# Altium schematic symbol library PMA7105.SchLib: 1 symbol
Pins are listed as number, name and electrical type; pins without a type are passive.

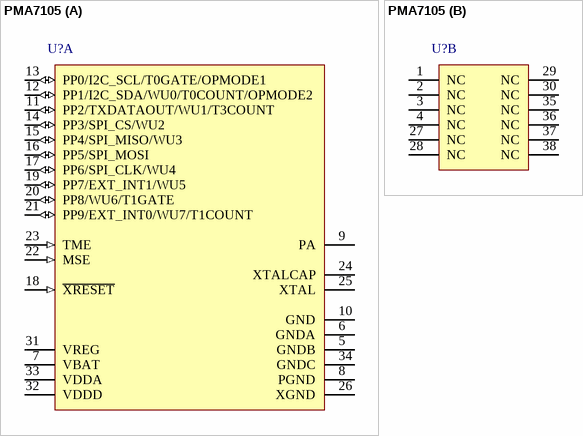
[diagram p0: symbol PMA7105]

## PMA7105
designator U?
RF Transmitter ASK / FSK 315 / 434 / 868 / 915 MHz, Embedded 8051 Microcontroller, 10-bit ADC, 125 kHz ASK LF Receiver, -40 to 85 degC, PG-TSSOP-38, Green; Manufacturer: Infineon; PartNumber: PMA7105; Channel Requirements per Band: Single Channel; Frequency Band: 315 MHz, 434 MHz, 868 MHz, 915 MHz; Green: yes; Transmit Power (at 3V): 5 dBm, 8 dBm, 10 dBm
footprint INF-PG-TSSOP-38_N (SOP, 38-Leads, Body 9.7x4.4 mm, Pitch 0.5 mm, IPC Medium Density)
footprint INF-PG-TSSOP-38_L (SOP, 38-Leads, Body 9.7x4.4 mm, Pitch 0.5 mm, IPC High Density)
footprint INF-PG-TSSOP-38_M (SOP, 38-Leads, Body 9.7x4.4 mm, Pitch 0.5 mm, IPC Low Density)
part A pins: 5 GNDB (power) "Ground", 6 GNDA (power) "Ground", 7 VBAT (power) "Battery Supply Voltage  Regulators", 8 PGND (power) "Power Amplifier Ground Double bond", 9 PA (oc) "Power Amplifier Output Stage", 10 GND (power) "Ground", 11 PP2/TXDATAOUT/WU1/T3COUNT (io) "PP2 -) Serial output of Manchester /  Biphase encoded data. -) GPIO -) External wake-up source 1 -) Clock source for Timer 3 -) Internal, switchable pull-up/pull-down.", 12 PP1/I2C_SDA/WU0/T0COUNT/OPMODE2 (io) "PP1 -) I2C bus interface data -) GPIO -) External wake-up source 0 -) Clock source for Timer 0 -) Select operation mode -) Internal, switchable pull-up/pull-down.", 13 PP0/I2C_SCL/T0GATE/OPMODE1 (io) "PP0 -) I2C bus interface clock -) GPIO -) External enable for Timer 0 -) Select operation mode -) Internal, switchable pull-up/pull-down.", 14 PP3/SPI_CS/WU2 (io) "PP3 -) SPI bus interface chip select -) GPIO -) External wake-up source 2 -) Internal, switchable pull-up/pull-down.", 15 PP4/SPI_MISO/WU3 (io) "PP4 -) SPI bus interface master in slave  out -) GPIO -) External wake-up source 3 -) Internal, switchable pull-up/pull-down.", 16 PP5/SPI_MOSI (io) "PP5 -) SPI bus interface master out  slave in -) GPIO -) Internal, switchable pull-up/pull-down.", 17 PP6/SPI_CLK/WU4 (io) "PP6 -) SPI bus interface clock -) GPIO -) External wake-up source 4 -) Internal, switchable pull-up/pull-down.", 18 ~{XRESET} (in) "External Reset Low active", 19 PP7/EXT_INT1/WU5 (io) "PP7 -) GPIO -) External interrupt source 1 -) External wake-up source 5 -) Internal, switchable pull-up/pull-down.", 20 PP8/WU6/T1GATE (io) "PP8 -) GPIO -) External wake-up source 6 -) External enable for Timer 1 -) Internal, switchable pull-up/pull-down.", 21 PP9/EXT_INT0/WU7/T1COUNT (io) "PP9 -) GPIO -) External interrupt source 0 -) External wake-up source 7 -) Clock source for Timer 1 -) Internal, switchable pull-up/pull-down.", 22 MSE (in) "Mode Select Enable High active,set to GND in NORMAL Mode.", 23 TME (in) "Test Mode Enable, n.a. for Normal Application Has to be set to GND in NORMAL Mode", 24 XTALCAP "Crystal Oscillator Load  Capacitance", 25 XTAL "Crystal Oscillator Input", 26 XGND (power) "Crystal Oscillator Ground", 31 VREG (power) "Internal Voltage Regulator  Output Connect to decoupling capacitor  (CBCAP =100 nF) Regulated Power supply.", 32 VDDD (power) "Digital Supply", 33 VDDA (power) "Analog Supply", 34 GNDC (power) "Ground"
part B pins: 1 NC "Not Connected", 2 NC "Not Connected", 3 NC "Not Connected", 4 NC "Not Connected", 27 NC "Not Connected", 28 NC "Not Connected", 29 NC "Not Connected", 30 NC "Not Connected", 35 NC "Not Connected", 36 NC "Not Connected", 37 NC "Not Connected", 38 NC "Not Connected"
